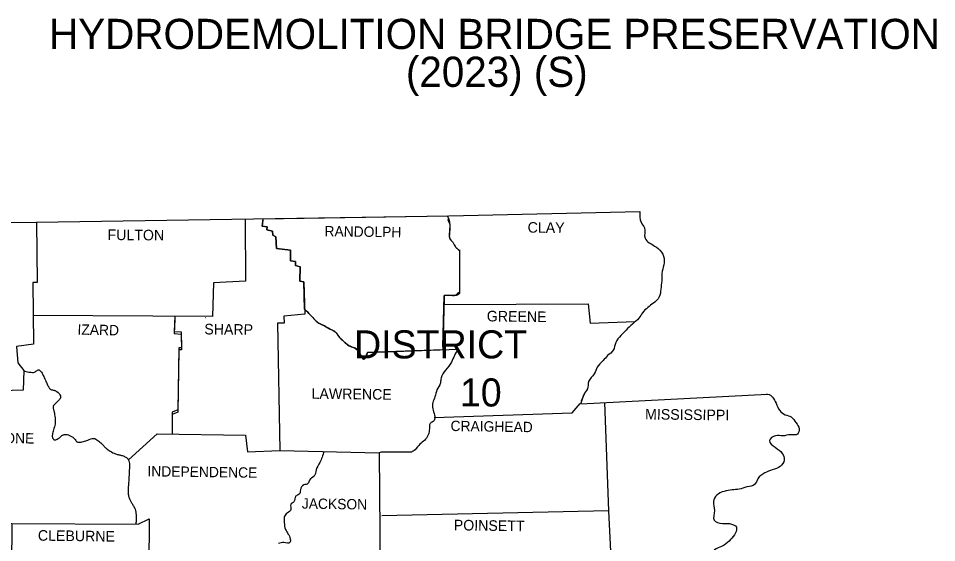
# Model space of a CAD drawing. Extents: x -24122 to 24238, y -8840 to 11381.
# Drawn here: x 13643 to 17292, y 9043 to 11124 of the extents above; entities that cross this region are included whole.
import ezdxf

# ---------------------------------------------------------------- set-up
doc = ezdxf.new("R2010")
doc.units = 0
for name, color, linetype in [('R_Border', 7, 'Continuous'), ('R_Grid', 7, 'Continuous'), ('S_AREA_CALC', 7, 'Continuous')]:
    doc.layers.add(name, color=color, linetype=linetype)

msp = doc.modelspace()

# ---------------------------------------------------------------- linework, layer by layer
at = {"layer": 'S_AREA_CALC'}
for p, q in [((14615.8, 10328.9), (15347.9, 10340.3)), ((15396.7, 10202.4), (15396.7, 10032.6)), ((15881, 9605.6), (15892.8, 9634)), ((15878.1, 9593.9), (15889.9, 9630.1))]:
    msp.add_line(p, q, dxfattribs=at)
for points in [[(10745.4, 10313), (12327.5, 10312), (13715.8, 10314.9), (15353.7, 10340.4), (16112.9, 10358)], [(14544.5, 10327.8), (14546.5, 10081.1), (14419.3, 10074.3), (14415.4, 9941.2), (13702.7, 9945.1)], [(14780.7, 9970.4), (14777.4, 10078.2), (14761.8, 10081.1), (14762.7, 10137.9), (14745.1, 10142.7), (14745.1, 10159.4), (14724.6, 10162.3), (14724.6, 10204.4), (14668.8, 10210.3), (14665.9, 10257.2), (14655.1, 10264.1), (14653.1, 10279.7), (14630.6, 10284.6), (14631.6, 10296.4), (14612.1, 10299.3), (14615.8, 10328.9)], [(13715.8, 10314.9), (13717.8, 10076.2), (13701.2, 10075.2), (13704.1, 9831.6), (13635.6, 9821.8), (13641.5, 9756.3), (13665, 9725.9), (13663, 9648.7), (13529.9, 9643.8), (13525, 9524.4), (13403.7, 9520.5), (13397.9, 9375.7), (13404.7, 9363.9), (13407.6, 9133), (13617, 9119.3), (13614.1, 8603.7), (13780.4, 8598.8), (13780.4, 8074.4), (13649.3, 8064.6), (13639.5, 7949.2), (13419.4, 7948.2)], [(14615, 10322.8), (14612.1, 10299.3), (14631.6, 10296.4), (14630.6, 10284.6), (14653.1, 10279.7), (14655.1, 10264.1), (14665.9, 10257.2), (14668.8, 10210.3), (14724.6, 10204.4), (14724.6, 10162.3), (14745.1, 10159.4), (14745.1, 10142.7), (14762.7, 10137.9), (14761.8, 10081.1), (14777.4, 10078.2), (14781.3, 9950), (14698.2, 9942.2), (14699.1, 9914.8), (14673.7, 9913.8), (14682.5, 9408.9), (15076.8, 9400.1), (15083.6, 8615.5), (14826.3, 8608.6), (14821.2, 8746.6)], [(15396.7, 10205.4), (15396.7, 10040)], [(15335.1, 10024.4), (15329.9, 9808.8), (15030.8, 9798.3)], [(15330.2, 9819.9), (15335.1, 10024.4), (15335.1, 9988.2), (15907.5, 9991.1), (15915.3, 9914.8), (16094.8, 9921.3)], [(14264.8, 9942), (14262.8, 9881.5), (14290.2, 9879.6), (14291.1, 9816.9), (14281.4, 9816.9), (14277.4, 9570.4), (14254.9, 9560.6), (14254.9, 9478.4)], [(14264.7, 9929.5), (14262.8, 9872.7), (14290.2, 9870.7), (14291.1, 9808.1), (14281.4, 9808.1), (14277.4, 9561.6), (14254.9, 9551.8), (14254.9, 9473.7)], [(14387, 9936.3), (14388, 9937.3)], [(15030.8, 9798.3), (15391.5, 9811)], [(15878.1, 9593.9), (16620.7, 9632)], [(15971.8, 9598.7), (15988.7, 9169.2), (16008.6, 8768.4)], [(15296.1, 9539.9), (15843.9, 9557.7), (15876.2, 9594.8)], [(14080.7, 9371.9), (14194.3, 9474.5), (14546.5, 9469.6), (14553.3, 9404), (14682.5, 9409)], [(15205, 9402.1), (15085.6, 9402.1), (15076.8, 9400.1)], [(15988.7, 9169.2), (15087.6, 9148.7)], [(13617, 9119.3), (14119.9, 9116.4), (14163, 9136.9), (14160, 8754.4), (14130.7, 8741.7), (14104.3, 8719.2), (14095.5, 8710.4), (14094.5, 8600.8), (13780.4, 8598.8)]]:
    msp.add_lwpolyline(points, dxfattribs=at)
for points in [[(15347.9, 10340.3), (15349.9, 10335.8), (15351.7, 10331.2), (15354.8, 10322), (15356.8, 10312.6), (15357.2, 10310.3), (15357.4, 10307.9), (15357.6, 10303.2), (15357.5, 10296.6), (15357.2, 10290), (15356.9, 10283.4), (15356.6, 10276.8), (15356.5, 10273.7), (15356, 10264.6), (15355.9, 10258.4), (15356.2, 10255.4), (15356.4, 10253.9), (15356.5, 10253.1), (15356.6, 10252.3), (15357.4, 10249.9), (15357.9, 10248.7), (15358.6, 10247.6), (15360.3, 10245.5), (15362, 10243.6), (15365.9, 10239.7), (15367.8, 10237.8), (15369.3, 10235.7), (15372.5, 10230.6), (15375.5, 10225.4), (15378.6, 10220.2), (15380.3, 10217.6), (15382.1, 10215.1), (15384.2, 10212.7), (15386.6, 10210.4), (15389.1, 10208.4), (15396.7, 10202.4)], [(15348.8, 10327.7), (15357.6, 10303.2), (15356.6, 10276.8), (15356.6, 10252.3), (15369.3, 10235.7), (15382.1, 10215.1), (15391.8, 10206.3)], [(16112.9, 10358), (16117.8, 10314.9), (16131.5, 10292.4), (16133.5, 10251.3), (16150.1, 10233.7), (16178.5, 10216.1), (16203.9, 10187.8), (16209.8, 10154.5), (16202, 10120.2), (16200, 10082.1), (16196.1, 10048.8), (16190.2, 10018.5), (16166.7, 9994), (16144.2, 9976.4), (16123.7, 9955.9), (16109, 9934.3), (16083.6, 9910.9), (16058.1, 9886.4), (16037.6, 9864.9), (16017, 9837.5), (16007.3, 9807.2), (15984.8, 9785.6), (15967.1, 9766.1), (15943.7, 9739.6), (15931.9, 9713.2), (15909.4, 9682.9), (15904.5, 9653.5), (15889.9, 9630.1), (15888.9, 9626.1)], [(15392.8, 10037.1), (15380.1, 10024.4), (15355.6, 10024.4), (15335.1, 10024.4)], [(15396.7, 10032.6), (15394.9, 10030.9), (15393, 10029.3), (15389, 10026.7), (15384.6, 10025), (15382.4, 10024.5), (15381.3, 10024.4), (15380.1, 10024.4), (15355.6, 10024.4), (15335.1, 10024.4)], [(15030.8, 9798.3), (15029.3, 9794.1), (15027.6, 9789.2), (15023.8, 9779.4), (15019.6, 9772.4), (15017.4, 9771.1), (15016.3, 9771.2), (15015.2, 9771.9), (15014.7, 9772.4), (15014.3, 9772.8), (15013.3, 9773.8), (15011.5, 9776), (15007.8, 9781.2), (15004.1, 9786.9), (15002.3, 9789.8), (15000.5, 9792.5), (14997.8, 9796.7), (14995.2, 9800.9), (14992.6, 9805.1), (14989.7, 9809.1), (14986.6, 9812.2), (14982.8, 9814.5), (14974.3, 9817.8), (14965.4, 9820.6), (14957.4, 9824.8), (14952.2, 9828.7), (14947, 9832.8), (14941.8, 9837), (14936.9, 9841.4), (14926.4, 9851.5), (14916.3, 9861.9), (14914.4, 9864.2), (14912.7, 9866.6), (14909.4, 9871.7), (14906, 9876.5), (14901.7, 9880.5), (14900.3, 9881.4), (14899, 9882.2), (14890.5, 9886.6), (14884.8, 9889.3), (14879.2, 9892.3), (14866.4, 9899.6), (14853.7, 9906.9), (14848.3, 9909.6), (14842.7, 9911.9), (14837.2, 9914.4), (14832.2, 9917.7), (14830.9, 9918.8), (14829.7, 9919.9), (14827.3, 9922.1), (14822.7, 9926.8), (14813.6, 9936.3), (14797.1, 9953.2), (14780.7, 9970.4)], [(14792.1, 9958.8), (14813.6, 9936.3), (14832.2, 9917.7), (14853.7, 9906.9), (14879.2, 9892.3), (14901.7, 9880.5), (14916.3, 9861.9), (14936.9, 9841.4), (14957.4, 9824.8), (14989.7, 9809.1), (15000.5, 9792.5), (15015.2, 9771.9), (15030.8, 9798.3)], [(15391.5, 9811), (15376.2, 9786.6), (15364.4, 9759.2), (15341, 9727.9), (15323.4, 9697.6), (15320.4, 9677), (15306.7, 9649.6), (15298.9, 9622.2), (15290.1, 9598.8), (15290.1, 9574.3), (15296.9, 9549.8), (15295, 9527.3), (15280.3, 9516.6), (15276.4, 9488.2), (15270.5, 9468.6), (15257.8, 9449.1), (15239.2, 9434.4), (15219.6, 9411.9), (15205, 9402.1)], [(13665, 9725.9), (13674.5, 9722.3), (13684.4, 9720.3), (13694.3, 9719.5), (13704.1, 9719.1), (13710.2, 9721.1), (13716.3, 9725.5), (13722.1, 9728.9), (13724.9, 9729.2), (13727.6, 9727.9), (13733.1, 9722.3), (13737.4, 9716), (13741, 9709.3), (13744.2, 9702.5), (13753, 9682.9), (13759.8, 9668.5), (13763.5, 9661.4), (13765.5, 9657.9), (13767.7, 9654.5), (13772.3, 9650.8), (13778.5, 9649.2), (13785.1, 9648), (13788.3, 9647.1), (13791.2, 9645.7), (13808.8, 9630.1), (13811.3, 9621.6), (13810.7, 9617.2), (13808.8, 9613.4), (13805.1, 9609.4), (13801.1, 9605.6), (13797, 9601.8), (13793.1, 9597.8), (13791.4, 9595.9), (13785.8, 9590.4), (13782.8, 9586.5), (13781.8, 9584.4), (13781.4, 9582.1), (13781.7, 9577.5), (13782.8, 9572.9), (13784.2, 9568.2), (13785.3, 9563.5), (13787.4, 9550.8), (13789.2, 9538.1), (13789.2, 9513.6), (13783.3, 9491.1), (13778.5, 9470.6), (13778, 9466.1), (13778.6, 9461.7), (13780.4, 9457.3), (13781.7, 9455.1), (13783.3, 9453), (13785.4, 9451.3), (13787.6, 9450.5), (13792.5, 9451.2), (13801.9, 9455.9), (13806.8, 9459.4), (13811.5, 9463.6), (13816.2, 9467.7), (13821.5, 9470.6), (13826.5, 9471.8), (13831.8, 9472.3), (13842, 9470.6), (13852.1, 9465.7), (13861.6, 9459.8), (13866.8, 9454.9), (13871.5, 9449), (13876.3, 9443.8), (13879.1, 9442.1), (13880.6, 9441.5), (13882.2, 9441.2), (13892.4, 9442.2), (13902.7, 9445.1), (13919.3, 9450), (13942.8, 9456.9), (13959.5, 9448.1), (13974.1, 9436.3), (13978.6, 9431.8), (13982.9, 9427), (13987.1, 9422.2), (13991.7, 9417.7), (14008.4, 9406), (14029.9, 9395.2), (14036.3, 9393.1), (14043, 9391.7), (14049.7, 9390.3), (14056.3, 9388.4), (14070.2, 9382.4), (14076.1, 9377.9), (14078.6, 9375.1), (14079.8, 9373.5), (14080.8, 9371.8), (14082.4, 9368.2), (14084.7, 9357.6), (14084.9, 9350.5), (14084.7, 9343.4), (14083.7, 9318.9), (14081.8, 9288.6), (14079.8, 9255.3), (14079.4, 9247.2), (14079.4, 9239.1), (14080.4, 9231), (14081.4, 9227), (14082.7, 9223), (14087.9, 9212), (14093.5, 9201.5), (14100.4, 9189), (14107.2, 9176.1), (14110.3, 9164.5), (14110.8, 9158.6), (14111.1, 9152.6), (14111.6, 9134.5), (14110.3, 9116.5)], [(16610, 9631), (16620.7, 9632), (16654, 9596.8), (16668.7, 9567.4), (16690.2, 9550.8), (16714.7, 9542), (16733.2, 9519.5), (16746, 9495), (16739.1, 9473.5), (16711.7, 9471.6), (16681.4, 9466.7), (16652, 9467.6), (16628.6, 9448.1), (16650.1, 9421.7), (16678.4, 9397.2), (16686.3, 9370.8), (16670.6, 9345.3), (16639.3, 9331.6), (16609, 9319.9), (16581.6, 9296.4), (16568.9, 9273.9), (16538.5, 9264.1), (16507.2, 9255.3), (16479.8, 9252.4), (16448.5, 9246.5), (16418.2, 9231.8), (16405.5, 9206.4), (16409.4, 9170.2), (16408.4, 9132.1), (16440.7, 9119.3), (16469.1, 9118.4), (16496.5, 9103.7), (16493.5, 9082.2), (16473, 9054.8), (16448.5, 9033.2), (16424.1, 9022.5), (16401.6, 9001.9), (16409.4, 8981.4), (16429.9, 8967.7), (16444.6, 8945.2), (16442.7, 8924.6), (16419.2, 8910), (16393.7, 8915.8), (16375.1, 8940.3), (16353.6, 8948.1), (16335, 8956.9), (16313.5, 8944.2), (16313.5, 8915.8), (16305.7, 8885.5), (16312.5, 8863), (16321.3, 8831.7), (16320.4, 8808.2), (16312.5, 8774.9), (16295.9, 8740.7), (16276.3, 8729.9), (16268.5, 8767.1), (16264.6, 8797.4), (16252.8, 8815), (16237.2, 8816), (16216.6, 8801.3), (16194.1, 8778.8), (16165.8, 8754.4), (16149.1, 8729.9), (16157.9, 8699.6), (16179.5, 8691.8), (16196.1, 8697.6), (16204.9, 8717.2), (16221.5, 8720.1), (16237.2, 8689.8)], [(14858.1, 9405.1), (14841, 9361), (14827.3, 9331.6), (14818.5, 9306.2), (14799.9, 9291.5), (14794, 9277.8), (14777.4, 9272), (14764.7, 9252.4), (14758.8, 9234.8), (14745.1, 9227), (14738.3, 9205.4), (14725.5, 9193.7), (14726.5, 9174.1), (14711.9, 9160.4), (14700.1, 9144.8), (14700.1, 9123.2), (14705, 9094.9), (14714.8, 9078.2), (14723.6, 9056.7), (14722.6, 9043), (14698.2, 9043), (14677.6, 9039.1)]]:
    msp.add_spline(points, degree=3, dxfattribs=at)

# ---------------------------------------------------------------- texts
at = {"layer": 'R_Border'}
for s, p in [('HYDRODEMOLITION BRIDGE PRESERVATION ', (13765.5, 11002.7)), ('(2023) (S)', (15183.3, 10852.4))]:
    msp.add_text(s, height=120, dxfattribs=at).set_placement(p)
for s, height, rotation, p in [('RANDOLPH', 41.09, 359.2583, (14859.6, 10259.2)), ('CLAY', 42.06, 359.2258, (15666.8, 10273.9)), ('FULTON', 42.06, 359.4996, (13997.6, 10244.5)), ('GREENE', 42.07, 359.2361, (15504.4, 9921.6)), ('IZARD', 41.08, 358.9258, (13878.2, 9868.8)), ('SHARP', 42.06, 359.3905, (14382.1, 9869.8)), ('LAWRENCE', 42.07, 359.2678, (14808.2, 9614.2)), ('MISSISSIPPI', 42.062, 359.3097, (16133.5, 9532.2)), ('CRAIGHEAD', 41.09, 359.1159, (15360.5, 9486.2)), ('STONE', 41.08, 359.4001, (13517.2, 9438.3)), ('INDEPENDENCE', 41.081, 359.2187, (14156.1, 9306.2)), ('JACKSON', 41.08, 359.1352, (14769.6, 9178)), ('POINSETT', 42.06, 359.1987, (15373.3, 9091.9)), ('CLEBURNE', 42.06, 359.2535, (13720.7, 9050.8))]:
    msp.add_text(s, height=height, rotation=rotation, dxfattribs=at).set_placement(p)
at = {"layer": 'R_Grid'}
for s, p in [('DISTRICT', (14977.3, 9774.3)), ('10', (15398, 9583.5))]:
    msp.add_text(s, height=111.54, dxfattribs=at).set_placement(p)

doc.saveas('drawing.dxf')
